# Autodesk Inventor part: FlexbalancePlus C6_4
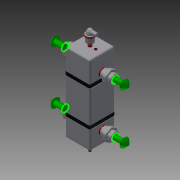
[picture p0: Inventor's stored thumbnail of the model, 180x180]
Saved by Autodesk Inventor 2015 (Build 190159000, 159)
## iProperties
allow_slope_adjustment: 0 ul
connection_type: 13 ul
flow_configuration2: 1 ul
flow_direction: 2 ul
loss_method: 0 ul
radius: 22,500 mm
description: 0:0:28379_Flexbalance Ecoplus C6_4
manufacturer: 0:0:Flamco Group
model: 0:0:Flexbalance
url: 0:0:http://www.flamcogroup.com
Created: 2015-10
Part Number: FlexbalancePlus C6_4
Material: Generic
Document SubType Name: Modeling
Designer: edwin
Density: 1 g/cm^3
Appearance: Default
Author: edwin
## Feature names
1. Revolution1
2. Revolution2
3. Extrusion1
4. Fillet1
5. Extrusion2
6. Circular Pattern1
7. Revolution3
8. Sweep1
9. Extrusion3
10. Extrusion4
11. Extrusion5
12. Rectangular Pattern1
13. Revolution4
14. Extrusion6
15. Circular Pattern2
16. Extrusion7
17. Circular Pattern3
18. Extrusion20
19. Circular Pattern9
20. Extrusion9
21. Rectangular Pattern2
22. Revolution5
23. Extrusion10
24. Circular Pattern5
25. Extrusion11
26. Circular Pattern6
27. Extrusion21
28. Circular Pattern10
29. Extrusion19
30. Rectangular Pattern4
31. Revolution6
32. Extrusion13
33. Circular Pattern8
34. Extrusion14
35. Fillet2
36. Extrusion15
37. Fillet3
38. Extrusion16
39. Extrusion17
40. Extrusion18
## Parameters: d0 = 90 deg, d1 = 90 deg, d2 = 42 mm, d5 = 0, d6 = 1.5 mm, d8 = 14 mm, d9 = 0, d11 = 360 deg, d13 = 90 deg, d14 = 15 mm, d15 = 252.5 mm, d16 = 0, d17 = 0, d19 = 0, d21 = 0, d22 = 2.5 mm, d24 = 0, d27 = 227 mm, d28 = 90 deg, d31 = 0, d33 = 360 deg, d37 = 0, d39 = 360 deg, d46 = 45 mm, d48 = 0, d52 = 90 deg, d56 = 0, d58 = 360 deg, d61 = 0, d63 = 360 deg, d73 = 90 deg, d75 = 5 mm, d76 = 0, d78 = 360 deg, d80 = 11.5 mm, d82 = 0, d83 = 1.5 mm, d84 = 15.5 mm, d86 = 0, d87 = 1 mm, d88 = 16.6 mm, d89 = 3.5 mm, d90 = 0, d91 = 9 mm, d92 = 0, d93 = 3 mm, d94 = 0, d95 = 45 mm, d97 = 0, d102 = 20.4 mm, d103 = 0, d105 = 360 deg, d107 = 20.4 mm, d108 = 0, d110 = 360 deg
